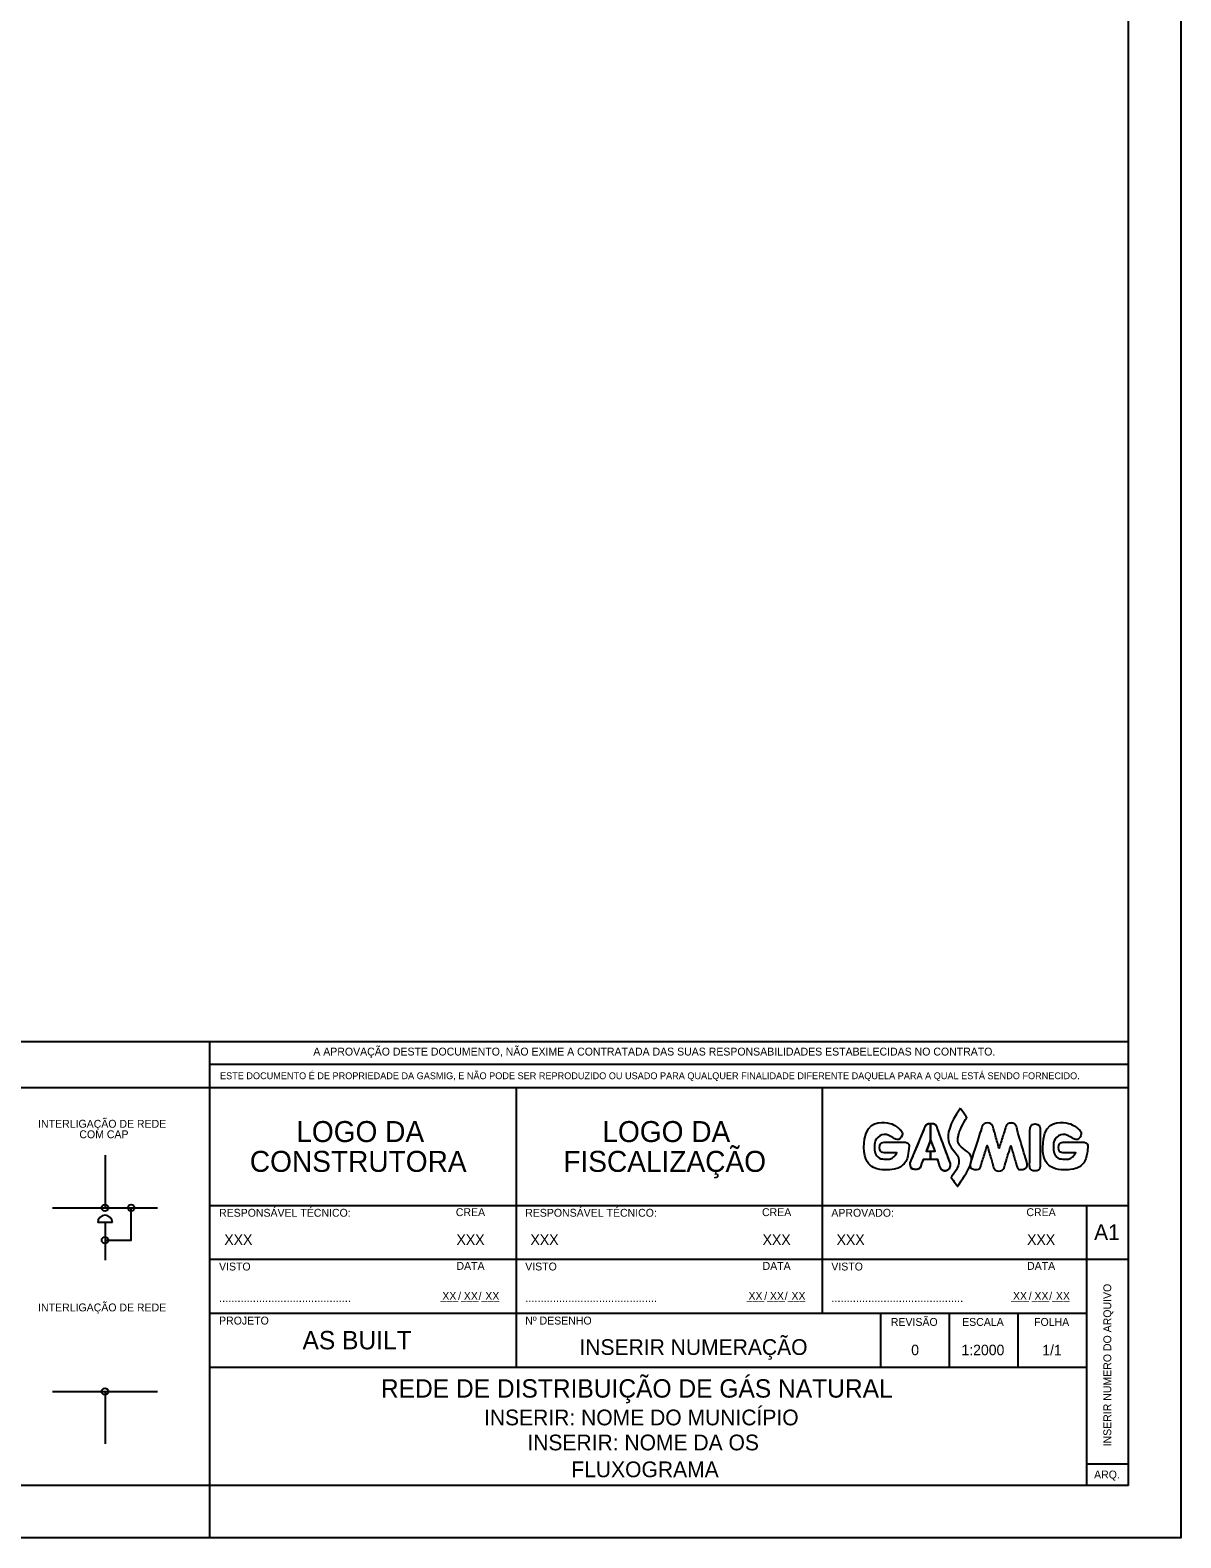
# Model space of a CAD drawing. Extents: x -1349 to -508, y 286 to 880.
# Drawn here: x -727.3 to -508, y 285.8 to 573.1 of the extents above; entities that cross this region are included whole.
import ezdxf

# ---------------------------------------------------------------- set-up
doc = ezdxf.new("R2010")
doc.units = 0
for name, color, linetype in [('FORMATO', 7, 'Continuous'), ('LEGENDA', 7, 'Continuous'), ('LOGO_GASMIG', 7, 'Continuous'), ('LOGO_GASMIG_2', 7, 'Continuous'), ('TEXTO', 7, 'Continuous')]:
    doc.layers.add(name, color=color, linetype=linetype)

# ---------------------------------------------------------------- blocks, each defined once
blk = doc.blocks.new('LOGO_GASMIG')
at = {"layer": 'LOGO_GASMIG'}
for p, q in [((-9.91, -2.5), (-7.76, 2.72)), ((-6.81, 3.52), (-6.81, 0.99)), ((-6.81, 0.99), (-6.81, 3.52)), ((-5.82, 2.7), (-3.85, -2.61)), ((-6.81, 0.99), (-7.48, -0.72)), ((-6.8, 1.01), (-6.81, 0.99)), ((-6.14, -0.72), (-6.8, 1.01)), ((-7.93, -2), (-8.2, -2.61)), ((-6.81, -2), (-7.93, -2)), ((-7.48, -0.72), (-6.81, -0.72)), ((-6.81, -0.72), (-6.81, -2)), ((-6.81, -2), (-6.81, -0.72)), ((-6.81, -0.72), (-6.14, -0.72)), ((-5.74, -2), (-6.81, -2)), ((-5.5, -2.71), (-5.74, -2)), ((-9.91, -2.71), (-9.91, -2.5)), ((-3.84, -2.62), (-3.84, -2.82))]:
    blk.add_line(p, q, dxfattribs=at)
for points, degree in [([(-2.28, 5.82), (-2.28, 5.82), (-1.32, 4.43), (-1.32, 4.43), (-1.32, 4.43), (-3.77, -0.08), (0.74, -1), (-2.73, -6.1), (-2.73, -6.1), (-2.73, -6.1), (-3.69, -4.71), (-3.69, -4.71), (-3.69, -4.71), (-1.24, -1.33), (-5.73, 0.93), (-2.28, 5.82)], 3), ([(-2.28, 5.82), (-2.28, 5.82), (-1.32, 4.43), (-1.32, 4.43), (-1.32, 4.43), (-3.77, -0.08), (0.74, -1), (-2.73, -6.1), (-2.73, -6.1), (-2.73, -6.1), (-3.69, -4.71), (-3.69, -4.71), (-3.69, -4.71), (-1.24, -1.33), (-5.73, 0.93), (-2.28, 5.82)], 3), ([(-16.99, -0.12), (-16.99, -2.13), (-15.43, -3.55), (-13.61, -3.55), (-13.61, -3.55), (-11.96, -3.55), (-10.38, -2.46), (-10.14, -0.35), (-10.14, -0.35), (-10.03, 0.17), (-10.38, 0.65), (-10.95, 0.65), (-10.95, 0.65), (-10.95, 0.65), (-13.57, 0.65), (-13.57, 0.65), (-13.57, 0.65), (-14.62, 0.65), (-14.64, -0.96), (-13.57, -0.96), (-13.57, -0.96), (-13.57, -0.96), (-12.12, -0.96), (-12.12, -0.96), (-12.12, -0.96), (-11.91, -0.94), (-12.02, -1.02), (-12.02, -1.08), (-12.02, -1.08), (-12.55, -1.8), (-13.09, -1.94), (-13.6, -1.93), (-13.6, -1.93), (-14.69, -1.93), (-15.37, -0.99), (-15.37, -0.15), (-15.37, -0.15), (-15.37, 1.2), (-13.84, 2.1), (-12.7, 1.41), (-12.7, 1.41), (-11.67, 0.76), (-10.85, 2.06), (-11.59, 2.68), (-11.59, 2.68), (-13.15, 3.99), (-16.94, 3.54), (-16.99, -0.12)], 3), ([(-16.99, -0.12), (-16.99, -2.13), (-15.43, -3.55), (-13.61, -3.55), (-13.61, -3.55), (-11.96, -3.55), (-10.38, -2.46), (-10.14, -0.35), (-10.14, -0.35), (-10.03, 0.17), (-10.38, 0.65), (-10.95, 0.65), (-10.95, 0.65), (-10.95, 0.65), (-13.57, 0.65), (-13.57, 0.65), (-13.57, 0.65), (-14.62, 0.65), (-14.64, -0.96), (-13.57, -0.96), (-13.57, -0.96), (-13.57, -0.96), (-12.12, -0.96), (-12.12, -0.96), (-12.12, -0.96), (-11.91, -0.94), (-12.02, -1.02), (-12.02, -1.08), (-12.02, -1.08), (-12.55, -1.8), (-13.09, -1.94), (-13.6, -1.93), (-13.6, -1.93), (-14.69, -1.93), (-15.37, -0.99), (-15.37, -0.15), (-15.37, -0.15), (-15.37, 1.2), (-13.84, 2.1), (-12.7, 1.41), (-12.7, 1.41), (-11.67, 0.76), (-10.85, 2.06), (-11.59, 2.68), (-11.59, 2.68), (-13.15, 3.99), (-16.94, 3.54), (-16.99, -0.12)], 3), ([(-6.81, -2), (-6.81, -2), (-6.81, -2), (-6.81, -2), (-6.81, -2), (-6.81, -2), (-7.93, -2), (-7.93, -2), (-7.93, -2), (-7.93, -2), (-8.2, -2.61), (-8.2, -2.61), (-8.2, -2.61), (-8.36, -3.19), (-8.61, -3.52), (-9.19, -3.49), (-9.19, -3.49), (-9.57, -3.49), (-9.88, -3.21), (-9.91, -2.71), (-9.91, -2.71), (-9.91, -2.71), (-9.91, -2.56), (-9.91, -2.56), (-9.91, -2.56), (-9.91, -2.54), (-9.91, -2.52), (-9.91, -2.5), (-9.91, -2.5), (-9.91, -2.5), (-9.91, -2.52), (-9.91, -2.5), (-9.91, -2.5), (-7.76, 2.72), (-7.76, 2.72), (-7.76, 2.72), (-7.61, 3.24), (-7.21, 3.51), (-6.81, 3.52)], 3), ([(-7.76, 2.72), (-7.61, 3.24), (-7.21, 3.51), (-6.81, 3.52)], 2), ([(-6.81, 3.52), (-6.38, 3.54), (-5.94, 3.27), (-5.82, 2.7), (-5.82, 2.7), (-5.82, 2.7), (-3.85, -2.61), (-3.85, -2.61), (-3.85, -2.61), (-3.85, -2.61), (-3.85, -2.62), (-3.84, -2.62), (-3.84, -2.62), (-3.84, -2.62), (-3.84, -2.82), (-3.84, -2.82), (-3.84, -2.82), (-3.94, -3.66), (-5.18, -3.83), (-5.5, -2.71), (-5.5, -2.71), (-5.5, -2.71), (-5.74, -2), (-5.74, -2), (-5.74, -2), (-5.74, -2), (-6.81, -2), (-6.81, -2), (-6.81, -2), (-6.81, -2), (-6.81, -2), (-6.81, -2)], 3), ([(-6.81, 3.52), (-6.38, 3.54), (-5.94, 3.27), (-5.82, 2.7)], 2), ([(-6.81, 0.99), (-6.81, 0.99), (-7.48, -0.72), (-7.48, -0.72), (-7.48, -0.72), (-7.48, -0.72), (-6.81, -0.72), (-6.81, -0.72), (-6.81, -0.72), (-6.81, -0.72), (-6.81, -0.72), (-6.81, -0.72)], 3), ([(-6.81, -0.72), (-6.81, -0.72), (-6.81, -0.72), (-6.81, -0.72), (-6.81, -0.72), (-6.81, -0.72), (-6.14, -0.72), (-6.14, -0.72), (-6.14, -0.72), (-6.14, -0.72), (-6.8, 1.01), (-6.8, 1.01), (-6.8, 1.01), (-6.8, 1.01), (-6.81, 0.99), (-6.81, 0.99)], 3), ([(-8.2, -2.61), (-8.36, -3.19), (-8.61, -3.52), (-9.19, -3.49), (-9.19, -3.49), (-9.57, -3.49), (-9.88, -3.21), (-9.91, -2.71)], 3), ([(-3.84, -2.82), (-3.94, -3.66), (-5.18, -3.83), (-5.5, -2.71)], 2), ([(-3.85, -2.61), (-3.85, -2.61), (-3.85, -2.62), (-3.84, -2.62)], 2)]:
    blk.add_open_spline(points, degree=degree, dxfattribs=at)
at = {"layer": 'LOGO_GASMIG_2'}
for points in [[(-0.74, -2.44), (-0.72, -2.36), (0.88, 2.54), (0.88, 2.54), (0.88, 2.54), (1.18, 3.63), (2.58, 3.63), (2.82, 2.52), (2.82, 2.52), (2.82, 2.52), (3.61, -0.26), (3.61, -0.26), (3.61, -0.26), (3.61, -0.26), (4.49, 2.5), (4.49, 2.5), (4.49, 2.5), (4.76, 3.63), (6.16, 3.61), (6.4, 2.48), (6.4, 2.48), (6.4, 2.48), (7.88, -2.56), (7.88, -2.56), (7.88, -2.56), (7.96, -2.89), (7.76, -3.37), (7.32, -3.48), (7.32, -3.48), (6.79, -3.6), (6.37, -3.34), (6.24, -2.7), (6.24, -2.7), (6.24, -2.7), (5.42, 0.09), (5.42, 0.09), (5.42, 0.09), (5.42, 0.09), (4.53, -2.69), (4.53, -2.69), (4.53, -2.69), (4.29, -3.79), (2.88, -3.79), (2.64, -2.67), (2.64, -2.67), (2.64, -2.67), (1.8, 0.14), (1.8, 0.14), (1.8, 0.14), (1.8, 0.14), (0.95, -2.61), (0.95, -2.61), (0.95, -2.61), (0.77, -3.19), (0.57, -3.55), (-0.04, -3.5), (-0.04, -3.5), (-0.53, -3.45), (-0.83, -3.13), (-0.74, -2.44)], [(-0.74, -2.44), (-0.72, -2.36), (0.88, 2.54), (0.88, 2.54), (0.88, 2.54), (1.18, 3.63), (2.58, 3.63), (2.82, 2.52), (2.82, 2.52), (2.82, 2.52), (3.61, -0.26), (3.61, -0.26), (3.61, -0.26), (3.61, -0.26), (4.49, 2.5), (4.49, 2.5), (4.49, 2.5), (4.76, 3.63), (6.16, 3.61), (6.4, 2.48), (6.4, 2.48), (6.4, 2.48), (7.88, -2.56), (7.88, -2.56), (7.88, -2.56), (7.96, -2.89), (7.76, -3.37), (7.32, -3.48), (7.32, -3.48), (6.79, -3.6), (6.37, -3.34), (6.24, -2.7), (6.24, -2.7), (6.24, -2.7), (5.42, 0.09), (5.42, 0.09), (5.42, 0.09), (5.42, 0.09), (4.53, -2.69), (4.53, -2.69), (4.53, -2.69), (4.29, -3.79), (2.88, -3.79), (2.64, -2.67), (2.64, -2.67), (2.64, -2.67), (1.8, 0.14), (1.8, 0.14), (1.8, 0.14), (1.8, 0.14), (0.95, -2.61), (0.95, -2.61), (0.95, -2.61), (0.77, -3.19), (0.57, -3.55), (-0.04, -3.5), (-0.04, -3.5), (-0.53, -3.45), (-0.83, -3.13), (-0.74, -2.44)], [(8.31, 2.45), (8.31, 0.66), (8.28, -2.72), (8.28, -2.72), (8.28, -2.72), (8.28, -3.78), (9.89, -3.78), (9.89, -2.72), (9.89, -2.72), (9.89, -2.72), (9.89, 2.47), (9.89, 2.47), (9.89, 2.47), (9.89, 3.52), (8.28, 3.52), (8.31, 2.45)], [(8.31, 2.45), (8.31, 0.66), (8.28, -2.72), (8.28, -2.72), (8.28, -2.72), (8.28, -3.78), (9.89, -3.78), (9.89, -2.72), (9.89, -2.72), (9.89, -2.72), (9.89, 2.47), (9.89, 2.47), (9.89, 2.47), (9.89, 3.52), (8.28, 3.52), (8.31, 2.45)], [(10.27, -0.12), (10.27, -2.13), (11.83, -3.55), (13.65, -3.55), (13.65, -3.55), (15.31, -3.55), (16.88, -2.46), (17.12, -0.35), (17.12, -0.35), (17.24, 0.17), (16.88, 0.65), (16.32, 0.65), (16.32, 0.65), (16.32, 0.65), (13.7, 0.65), (13.7, 0.65), (13.7, 0.65), (12.64, 0.65), (12.62, -0.96), (13.7, -0.96), (13.7, -0.96), (13.7, -0.96), (15.15, -0.96), (15.15, -0.96), (15.15, -0.96), (15.36, -0.94), (15.24, -1.02), (15.24, -1.08), (15.24, -1.08), (14.71, -1.8), (14.18, -1.94), (13.67, -1.93), (13.67, -1.93), (12.57, -1.93), (11.9, -0.99), (11.9, -0.15), (11.9, -0.15), (11.9, 1.2), (13.42, 2.1), (14.57, 1.41), (14.57, 1.41), (15.6, 0.76), (16.42, 2.06), (15.67, 2.68), (15.67, 2.68), (14.12, 3.99), (10.32, 3.54), (10.27, -0.12)], [(10.27, -0.12), (10.27, -2.13), (11.83, -3.55), (13.65, -3.55), (13.65, -3.55), (15.31, -3.55), (16.88, -2.46), (17.12, -0.35), (17.12, -0.35), (17.24, 0.17), (16.88, 0.65), (16.32, 0.65), (16.32, 0.65), (16.32, 0.65), (13.7, 0.65), (13.7, 0.65), (13.7, 0.65), (12.64, 0.65), (12.62, -0.96), (13.7, -0.96), (13.7, -0.96), (13.7, -0.96), (15.15, -0.96), (15.15, -0.96), (15.15, -0.96), (15.36, -0.94), (15.24, -1.02), (15.24, -1.08), (15.24, -1.08), (14.71, -1.8), (14.18, -1.94), (13.67, -1.93), (13.67, -1.93), (12.57, -1.93), (11.9, -0.99), (11.9, -0.15), (11.9, -0.15), (11.9, 1.2), (13.42, 2.1), (14.57, 1.41), (14.57, 1.41), (15.6, 0.76), (16.42, 2.06), (15.67, 2.68), (15.67, 2.68), (14.12, 3.99), (10.32, 3.54), (10.27, -0.12)]]:
    blk.add_open_spline(points, degree=3, dxfattribs=at)

msp = doc.modelspace()

# ---------------------------------------------------------------- linework, layer by layer
at = {"layer": 'FORMATO'}
msp.add_line((-518.04, 295.82), (-1344.05, 295.82), dxfattribs=at)
msp.add_lwpolyline([(-1349.05, 879.82), (-508.05, 879.82), (-508.05, 285.82), (-1349.05, 285.82)], close=True, dxfattribs=at)
for points in [[(-518.04, 295.82), (-518.04, 869.82), (-1324.05, 869.82), (-1324.05, 295.82)], [(-518.04, 380.36), (-1324.05, 380.36)], [(-693.05, 295.82), (-693.05, 380.36)], [(-693.05, 376.11), (-518.04, 376.11)], [(-1324.05, 371.63), (-693.05, 371.63)], [(-693.05, 371.63), (-518.04, 371.63)], [(-634.71, 371.63), (-634.71, 318.34)], [(-576.38, 371.63), (-576.38, 328.64)], [(-693.05, 349.18), (-518.04, 349.18)], [(-525.98, 295.82), (-525.98, 349.18)], [(-693.05, 338.94), (-518.04, 338.94)], [(-693.05, 328.64), (-525.98, 328.64)], [(-565.19, 318.34), (-565.19, 328.64)], [(-552.12, 318.34), (-552.12, 328.64)], [(-539.05, 318.34), (-539.05, 328.64)], [(-693.05, 318.34), (-525.98, 318.34)], [(-525.98, 299.94), (-518.04, 299.94)], [(-693.05, 285.82), (-693.05, 295.82)]]:
    msp.add_lwpolyline(points, dxfattribs=at)
at = {"layer": 'LEGENDA'}
for points in [[(-713.05, 358.72), (-713.05, 348.72)], [(-723.05, 348.72), (-703.05, 348.72)], [(-713.05, 342.55), (-708.05, 342.55), (-708.05, 348.72)], [(-711.65, 345.89), (-714.45, 345.89)], [(-713.05, 345.89), (-713.05, 338.72)], [(-723.05, 313.72), (-703.05, 313.72)], [(-713.05, 313.72), (-713.05, 303.72)]]:
    msp.add_lwpolyline(points, dxfattribs=at)
for centre in [(-713.05, 348.72), (-708.05, 348.72), (-713.05, 342.55), (-713.05, 313.72)]:
    msp.add_circle(centre, 0.633, dxfattribs=at)
msp.add_arc((-713.05, 345.89), 1.4, 0, 180, dxfattribs=at)

# ---------------------------------------------------------------- block references
at = {"layer": 'LOGO_GASMIG', "xscale": 1.25, "yscale": 1.25}
msp.add_blockref('LOGO_GASMIG', (-547.21, 360.4), dxfattribs=at)

# ---------------------------------------------------------------- texts
at = {"layer": 'FORMATO'}
for s, height, rotation, p in [('A APROVAÇÃO DESTE DOCUMENTO, NÃO EXIME A CONTRATADA DAS SUAS RESPONSABILIDADES ESTABELECIDAS NO CONTRATO.', 1.5, 360, (-673.36, 377.73)), ('INSERIR NUMERO DO ARQUIVO', 1.5, 90, (-521.31, 303.25)), ('AS BUILT ', 3.5, 360, (-675.42, 321.74)), ('REDE DE DISTRIBUIÇÃO DE GÁS NATURAL', 3.5, 360, (-660.48, 312.54)), ('ARQ.', 1.5, 360, (-524.58, 297.13))]:
    msp.add_text(s, height=height, rotation=rotation, dxfattribs=at).set_placement(p)
for s, height, p in [('ESTE DOCUMENTO É DE PROPRIEDADE DA GASMIG, E NÃO PODE SER REPRODUZIDO OU USADO PARA QUALQUER FINALIDADE DIFERENTE DAQUELA PARA A QUAL ESTÁ SENDO FORNECIDO.', 1.3, (-691.14, 373.22)), ('RESPONSÁVEL TÉCNICO:', 1.5, (-691.32, 347.01)), ('CREA', 1.5, (-646.2, 347.13)), ('RESPONSÁVEL TÉCNICO:', 1.5, (-632.98, 347.01)), ('CREA', 1.5, (-587.86, 347.13)), ('APROVADO:', 1.5, (-574.65, 347.01)), ('CREA', 1.5, (-537.47, 347.13)), ('A1', 3, (-524.58, 342.56)), ('VISTO', 1.5, (-691.32, 336.77)), ('DATA', 1.5, (-646.08, 336.89)), ('VISTO', 1.5, (-632.98, 336.77)), ('DATA', 1.5, (-587.75, 336.89)), ('VISTO', 1.5, (-574.65, 336.77)), ('DATA', 1.5, (-537.35, 336.89)), ('...........................................', 1.573, (-691.32, 330.75)), ('___/___/___', 1.5, (-649.11, 331.18)), ('...........................................', 1.573, (-632.98, 330.75)), ('___/___/___', 1.5, (-590.77, 331.18)), ('...........................................', 1.573, (-574.65, 330.75)), ('___/___/___', 1.5, (-540.38, 331.18)), ('PROJETO', 1.5, (-691.32, 326.47)), ('Nº DESENHO', 1.5, (-632.98, 326.47)), ('REVISÃO', 1.5, (-563.31, 326.21)), ('ESCALA', 1.5, (-549.72, 326.21)), ('FOLHA', 1.5, (-536.01, 326.21)), ('INSERIR NUMERAÇÃO', 3, (-622.65, 320.67)), ('0', 2, (-559.43, 320.62)), ('1:2000', 2, (-549.86, 320.62)), ('1/1', 2, (-534.46, 320.6)), ('INSERIR: NOME DO MUNICÍPIO', 3, (-640.84, 307.26)), ('INSERIR: NOME DA OS', 3, (-632.58, 302.49)), ('FLUXOGRAMA', 3, (-624.2, 297.37))]:
    msp.add_text(s, height=height, dxfattribs=at).set_placement(p)
at = {"layer": 'LEGENDA'}
for s, p in [('INTERLIGAÇÃO DE REDE', (-725.8, 363.97)), ('COM CAP', (-717.94, 361.97)), ('INTERLIGAÇÃO DE REDE', (-725.8, 328.97))]:
    msp.add_text(s, height=1.5, dxfattribs=at).set_placement(p)
at = {"layer": 'TEXTO'}
for s, height, p in [('LOGO DA', 4, (-676.61, 361.24)), ('LOGO DA', 4, (-618.28, 361.24)), ('CONSTRUTORA', 4, (-685.46, 355.56)), ('FISCALIZAÇÃO', 4, (-625.73, 355.56)), ('XXX', 2, (-690.32, 341.64)), ('XXX', 2, (-646.08, 341.64)), ('XXX', 2, (-631.98, 341.64)), ('XXX', 2, (-587.75, 341.64)), ('XXX', 2, (-573.65, 341.64)), ('XXX', 2, (-537.35, 341.64)), ('XX', 1.5, (-648.78, 331.18)), ('XX', 1.5, (-644.68, 331.18)), ('XX', 1.5, (-640.59, 331.18)), ('XX', 1.5, (-590.44, 331.18)), ('XX', 1.5, (-586.35, 331.18)), ('XX', 1.5, (-582.25, 331.18)), ('XX', 1.5, (-540.04, 331.18)), ('XX', 1.5, (-535.95, 331.18)), ('XX', 1.5, (-531.86, 331.18))]:
    msp.add_text(s, height=height, dxfattribs=at).set_placement(p)

doc.saveas('drawing.dxf')
